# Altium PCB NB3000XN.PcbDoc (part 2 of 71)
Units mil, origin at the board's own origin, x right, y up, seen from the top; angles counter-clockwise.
Board outline 9527.56 x 6929.77 mil, 6 copper layers (Top Layer, GND+SHIELD, MidLayer1, MidLayer2, P2 - 3V3+5V0, Bottom Layer), stack 62.375 mil thick; 832 components, 1027 nets, 4655 pads, 4981 vias.
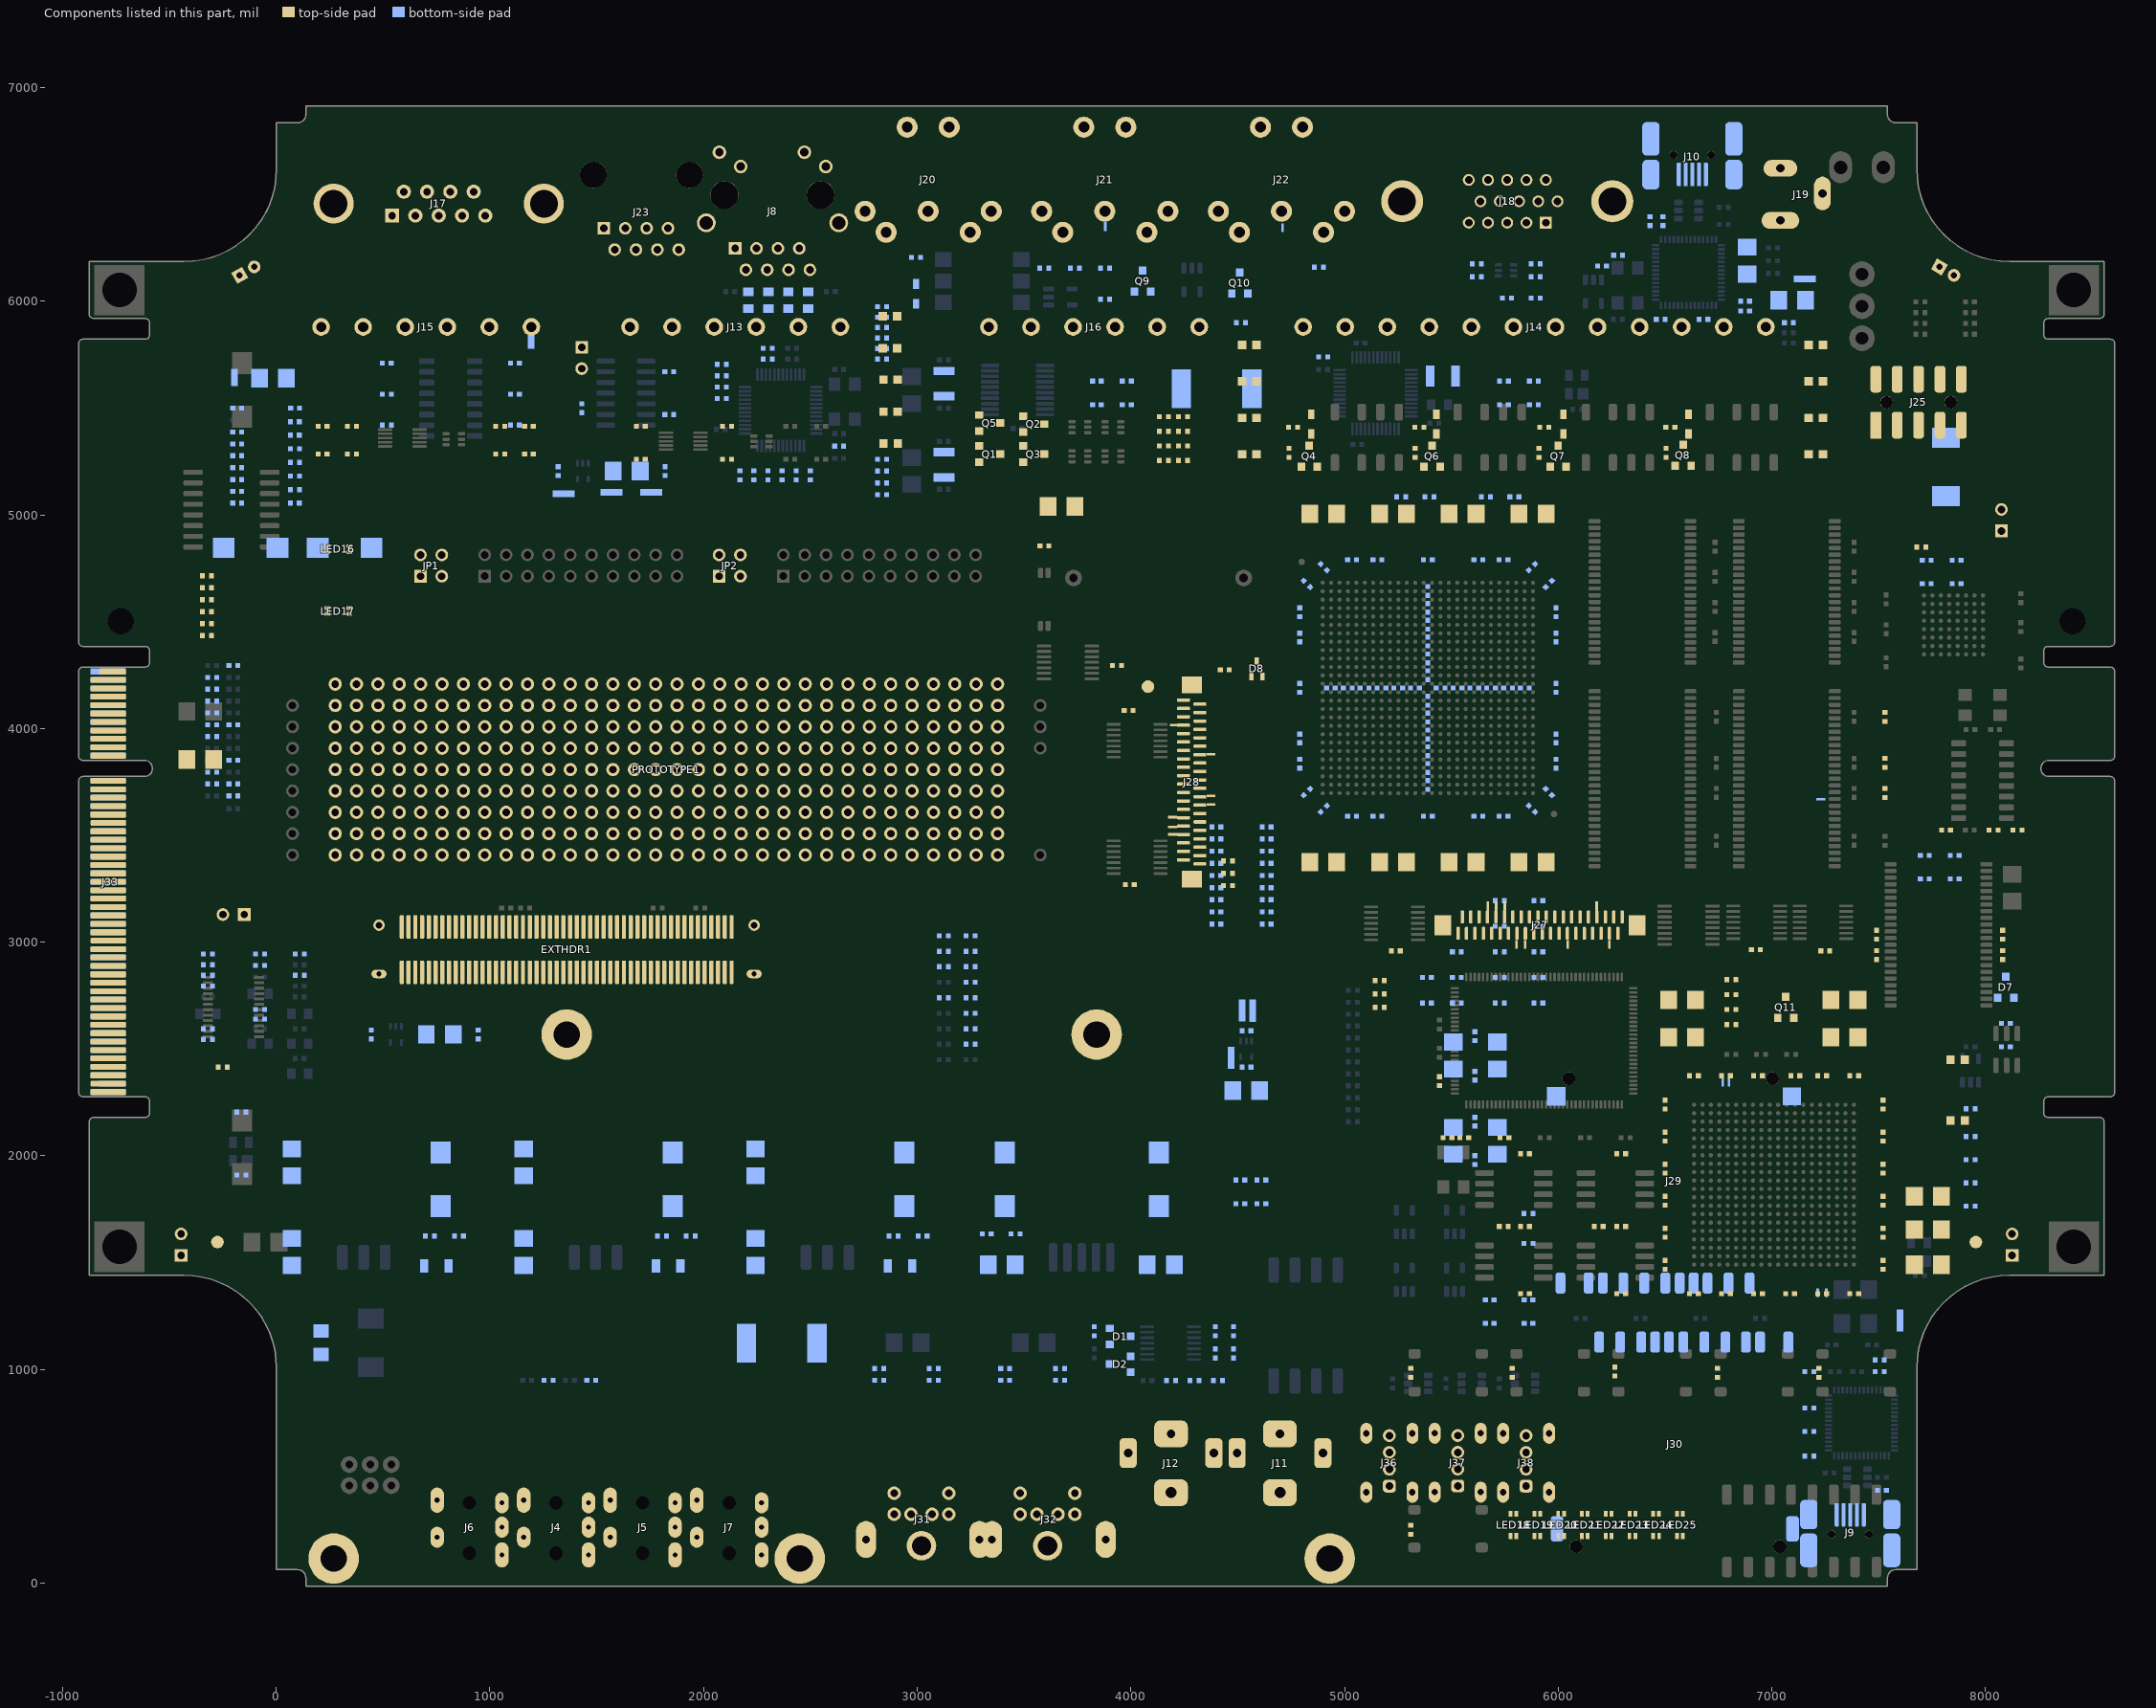
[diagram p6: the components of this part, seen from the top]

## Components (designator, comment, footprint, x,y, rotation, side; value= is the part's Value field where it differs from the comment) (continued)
C106 "220uF 10V" CAPC7343-STAR -120,4845 r180 bottom locked (schematic designator C12)
C107 "220uF 10V" CAPC7343-STAR 320,4845 r180 bottom locked (schematic designator C16)
C108 "1uF 10V" CAPC1005-STAR#1 87.46,5372.94 r180 bottom locked (schematic designator C10)
C109 "1uF 10V" CAPC1005-STAR#1 87.46,5055.08 r0 bottom locked (schematic designator C18)
C110 "1uF 10V" CAPC1005-STAR#1 -182.03,5055.08 r180 bottom locked (schematic designator C14)
C111 "10uF 20V" CAPC3528-STAR#1 -15,5640 r0 bottom locked (schematic designator C23)
C112 "0.1uF 16V" CAPC1005-STAR#1 87.97,5500.08 r180 bottom locked (schematic designator C24)
C113 "0.1uF 16V" CAPC1005-STAR#1 -182.03,5500.08 r180 bottom locked (schematic designator C25)
C114 "0.1uF 16V" CAPC1005-STAR#1 87.46,5436.51 r0 bottom locked (schematic designator C28)
C115 "10uF 20V" CAPC3528-STAR#1 3675,5040 r0 top locked (schematic designator C2)
C116 "0.1uF 16V" CAPC1005-STAR#1 3595,4855 r180 top locked (schematic designator C3)
C117 "33nF 25V" CAPC1005-STAR#1 217,5415 r180 top locked (schematic designator C1)
C118 "33nF 25V" CAPC1005-STAR#1 1183,5415 r0 top locked (schematic designator C2)
C119 "33nF 25V" CAPC1005-STAR#1 1183,5285 r0 top locked (schematic designator C3)
C120 "33nF 25V" CAPC1005-STAR#1 217,5285 r180 top locked (schematic designator C4)
C121 "1uF 10V" CAPC1005-STAR#1 3990,4085 r0 top locked (schematic designator C1)
C122 "1uF 10V" CAPC1005-STAR#1 5240,2960 r0 top locked (schematic designator C1)
C123 "1uF 10V" CAPC1005-STAR#1 6925,2965 r180 top locked (schematic designator C1)
C124 "1uF 10V" CAPC1005-STAR#1 3995,3270 r0 top locked (schematic designator C1)
C125 "1uF 10V" CAPC1005-STAR#1 7250,2960 r0 top locked (schematic designator C1)
C126 "10uF 20V" CAPC3528-STAR#1 2243.07,1550 r90 bottom locked (schematic designator C1)
C127 "1uF 25V" CAPC3216-STAR 2920,1485 r0 bottom locked (schematic designator C2)
C128 "10uF 20V" CAPC3528-STAR#1 2243.07,1970 r90 bottom locked (schematic designator C3)
C129 "220uF 10V" CAPC7343-STAR 2940,1890 r90 bottom locked (schematic designator C4)
C130 "10uF 20V" CAPC3528-STAR#1 1158.07,1550 r90 bottom locked (schematic designator C1)
C131 "1uF 25V" CAPC3216-STAR 1835,1485 r0 bottom locked (schematic designator C2)
C132 "10uF 20V" CAPC3528-STAR#1 1158.07,1970 r90 bottom locked (schematic designator C3)
C133 "220uF 10V" CAPC7343-STAR 1855,1890 r90 bottom locked (schematic designator C4)
C134 "10uF 20V" CAPC3528-STAR#1 73.07,1550 r90 bottom locked (schematic designator C1)
C135 "1uF 25V" CAPC3216-STAR 750,1485 r0 bottom locked (schematic designator C2)
C136 "10uF 20V" CAPC3528-STAR#1 73.07,1970 r90 bottom locked (schematic designator C3)
C137 "220uF 10V" CAPC7343-STAR 770,1890 r90 bottom locked (schematic designator C4)
C138 "220uF 10V" CAPC7343-STAR 4130,1890 r90 bottom locked (schematic designator C1)
C139 "10uF 20V" CAPC3528-STAR#1 4140,1490 r0 bottom locked (schematic designator C2)
C140 "10uF 20V" CAPC3528-STAR#1 3395,1490 r180 bottom locked (schematic designator C3)
C141 "220uF 10V" CAPC7343-STAR 3409.45,1890 r90 bottom locked (schematic designator C4)
C142 "1uF 10V" CAPC1005-STAR#1 4540.98,2585 r180 bottom locked (schematic designator C1)
C143 "10uF 20V" CAPC3528-STAR#1 4540,2305 r0 bottom locked (schematic designator C2)
C144 "1uF 10V" CAPC1005-STAR#1 4540.98,2415 r180 bottom locked (schematic designator C3)
C145 "1uF 10V" CAPC1005-STAR#1 445,2568.37 r270 bottom locked (schematic designator C1)
C146 "10uF 20V" CAPC3528-STAR#2 765.49,2568.37 r180 bottom locked (schematic designator C2)
C147 "1uF 10V" CAPC1005-STAR#1 945,2568.37 r270 bottom locked (schematic designator C3)
C148 "0.1uF 16V" CAPC1005-STAR#1 1117.11,5710.08 r0 bottom locked (schematic designator C1)
C149 "0.1uF 16V" CAPC1005-STAR#1 517.11,5710.08 r0 bottom locked (schematic designator C3)
C150 "0.1uF 16V" CAPC1005-STAR#1 1117.11,5565.08 r0 bottom locked (schematic designator C2)
C151 "0.1uF 16V" CAPC1005-STAR#1 1117.11,5420.08 r0 bottom locked (schematic designator C4)
C152 "1uF 10V" CAPC1005-STAR#1 1840,5470 r0 bottom locked (schematic designator C1)
C153 "0.1uF 16V" CAPC1005-STAR#1 8080,3035 r90 top locked (schematic designator C1_SM)
C154 "0.1uF 16V" CAPC1005-STAR#1 8080,2940 r90 top locked (schematic designator C2_SM)
C155 "10nF 16V" CAPC1005-STAR#1 7490,2940 r90 top locked (schematic designator C3_SM)
C156 "10nF 16V" CAPC1005-STAR#1 7490,3035 r270 top locked (schematic designator C4_SM)
C157 "22pF 50V" CAPC1005-STAR#1 5482,2085 r180 top locked (schematic designator C344)
C158 "10nF 16V" CAPC1005-STAR#1 5745,1670 r0 top locked (schematic designator C1)
C159 "0.1uF 16V" CAPC1005-STAR#1 5845,2010 r180 top locked (schematic designator C2)
C160 "10nF 16V" CAPC1005-STAR#1 6190,1670 r180 top locked (schematic designator C1)
C161 "0.1uF 16V" CAPC1005-STAR#1 6295,1355 r0 top locked (schematic designator C2)
C162 "10nF 16V" CAPC1005-STAR#1 6295,2010 r180 top locked (schematic designator C1)
C163 "0.1uF 16V" CAPC1005-STAR#1 6295,1670 r180 top locked (schematic designator C2)
C164 "10nF 16V" CAPC1005-STAR#1 5845,1670 r180 top locked (schematic designator C3)
C165 "0.1uF 16V" CAPC1005-STAR#1 5845,1355 r180 top locked (schematic designator C4)
C166 "22pF 50V" CAPC1005-STAR#1 6430,6375 r90 bottom locked (schematic designator C1)
C167 "22pF 50V" CAPC1005-STAR#1 6490,6375 r90 bottom locked (schematic designator C2)
C168 "0.1uF 16V" CAPC1005-STAR#1 6280,6215 r180 bottom locked (schematic designator C3)
C169 "22pF 50V" CAPC1005-STAR#1 5560,2085 r180 top locked (schematic designator C345)
C170 "0.1uF 16V" CAPC1005-STAR#1 7080,5900 r180 bottom locked (schematic designator C2)
C171 "10uF 20V" CAPC3528-STAR#1 7095,6005 r0 bottom locked (schematic designator C6)
C172 "0.1uF 16V" CAPC1005-STAR#1 6205,6165 r180 bottom locked (schematic designator C3)
C173 "0.1uF 16V" CAPC1005-STAR#1 6680,5915 r0 bottom locked (schematic designator C4)
C174 "0.1uF 16V" CAPC1005-STAR#1 6480,5915 r180 bottom locked (schematic designator C5)
C175 "10uF 20V" CAPC3528-STAR#1 6885,6190 r90 bottom locked (schematic designator C7)
C176 "0.1uF 16V" CAPC1005-STAR#1 6875,5955 r180 bottom locked (schematic designator C8)
C177 "0.1uF 16V" CAPC1005-STAR#1 6875,6000 r180 bottom locked (schematic designator C9)
C181 "1uF 10V" CAPC1005-STAR#1 1320,5205 r270 bottom locked (schematic designator C1)
C182 "10uF 20V" CAPC3528-STAR#1 1640.49,5205 r180 bottom locked (schematic designator C2)
C183 "1uF 10V" CAPC1005-STAR#1 1820,5205 r270 bottom locked (schematic designator C3)
C184 "10uF 20V" CAPC3528-STAR#1 7340,2730 r0 top locked (schematic designator C42_FP)
C185 "10uF 20V" CAPC3528-STAR#1 5715,2070 r270 bottom locked (schematic designator C343)
C186 "220nF 16V" CAPC1005-STAR#1 5445,2350 r270 top locked (schematic designator C205)
C187 "0.1uF 16V" CAPC1005-STAR#1 5748.74,2085 r0 top locked (schematic designator C204)
C189 "10uF 20V" CAPC3528-STAR#1 6580,2730 r180 top locked (schematic designator C1_FP)
C190 "10uF 20V" CAPC3528-STAR#1 7730,1810 r0 top locked (schematic designator C2_FP)
C191 "10uF 20V" CAPC3528-STAR#1 -355,3855 r180 top locked (schematic designator C3_FP)
C192 "0.1uF 16V" CAPC1005-STAR#1 5386.06,2715 r0 bottom locked (schematic designator C5_FP)
C193 "0.1uF 16V" CAPC1005-STAR#1 5386.06,2835 r0 bottom locked (schematic designator C8_FP)
C194 "0.1uF 16V" CAPC1005-STAR#1 7520,1940 r90 top locked (schematic designator C9_FP)
C195 "0.1uF 16V" CAPC1005-STAR#1 7520,1790 r270 top locked (schematic designator C11_FP)
C196 "10nF 16V" CAPC1005-STAR#1 6935,2375 r180 top locked (schematic designator C13_FP)
C197 "10nF 16V" CAPC1005-STAR#1 7110,2375 r0 top locked (schematic designator C15_FP)
C198 "10nF 16V" CAPC1005-STAR#1 6935,1355 r180 top locked (schematic designator C16_FP)
C199 "10nF 16V" CAPC1005-STAR#1 7085,1355 r0 top locked (schematic designator C18_FP)
C200 "10uF 20V" CAPC3528-STAR#1 7730,1655 r0 top locked (schematic designator C38_FP)
C201 "10uF 20V" CAPC3528-STAR#1 7340,2555 r0 top locked (schematic designator C39_FP)
C202 "10uF 20V" CAPC3528-STAR#1 6580,2555 r180 top locked (schematic designator C40_FP)
C203 "10uF 20V" CAPC3528-STAR#1 7730,1490 r0 top locked (schematic designator C41_FP)
C215 "0.1uF 16V" CAPC1005-STAR#1 6635,2375 r0 top locked (schematic designator C46_FP)
C216 "0.1uF 16V" CAPC1005-STAR#1 4512.39,1776.18 r180 bottom locked (schematic designator C47_FP)
C217 "0.1uF 16V" CAPC1005-STAR#1 7235,2375 r0 top locked (schematic designator C48_FP)
C218 "0.1uF 16V" CAPC1005-STAR#1 7520,2240 r90 top locked (schematic designator C49_FP)
C219 "0.1uF 16V" CAPC1005-STAR#1 5679.72,1326.18 r0 bottom locked (schematic designator C50_FP)
C220 "0.1uF 16V" CAPC1005-STAR#1 7520,1640 r90 top locked (schematic designator C51_FP)
C221 "0.1uF 16V" CAPC1005-STAR#1 6635,1355 r0 top locked (schematic designator C52_FP)
C222 "0.1uF 16V" CAPC1005-STAR#1 7716.06,3296.18 r180 bottom locked (schematic designator C53_FP)
C223 "0.1uF 16V" CAPC1005-STAR#1 7235,1355 r0 top locked (schematic designator C54_FP)
C224 "0.1uF 16V" CAPC1005-STAR#1 6500,2240 r90 top locked (schematic designator C55_FP)
C225 "0.1uF 16V" CAPC1005-STAR#1 5886.06,5626.18 r180 bottom locked (schematic designator C56_FP)
C226 "0.1uF 16V" CAPC1005-STAR#1 5886.06,5516.18 r180 bottom locked (schematic designator C57_FP)
C227 "0.1uF 16V" CAPC1005-STAR#1 7724.33,4788 r180 bottom locked (schematic designator C58_FP)
C228 "0.1uF 16V" CAPC1005-STAR#1 7724.33,4678 r180 bottom locked (schematic designator C59_FP)
C229 "0.1uF 16V" CAPC1005-STAR#1 3981.06,5626.18 r180 bottom locked (schematic designator C60_FP)
C231 "10nF 16V" CAPC1005-STAR#1 6785,2375 r0 top locked (schematic designator C62_FP)
C232 "10nF 16V" CAPC1005-STAR#1 4512.39,1886.18 r180 bottom locked (schematic designator C63_FP)
C233 "10nF 16V" CAPC1005-STAR#1 7385,2375 r0 top locked (schematic designator C64_FP)
C234 "10nF 16V" CAPC1005-STAR#1 7520,2090 r90 top locked (schematic designator C65_FP)
C235 "10nF 16V" CAPC1005-STAR#1 5679.72,1216.18 r0 bottom locked (schematic designator C66_FP)
C236 "10nF 16V" CAPC1005-STAR#1 7520,1490 r90 top locked (schematic designator C67_FP)
C237 "10nF 16V" CAPC1005-STAR#1 6785,1355 r0 top locked (schematic designator C68_FP)
C238 "10nF 16V" CAPC1005-STAR#1 7716.06,3406.18 r180 bottom locked (schematic designator C69_FP)
C239 "10nF 16V" CAPC1005-STAR#1 7385,1355 r0 top locked (schematic designator C70_FP)
C240 "10nF 16V" CAPC1005-STAR#1 6500,2090 r90 top locked (schematic designator C71_FP)
C241 "10nF 16V" CAPC1005-STAR#1 6500,1790 r90 top locked (schematic designator C73_FP)
C242 "10nF 16V" CAPC1005-STAR#1 6500,1490 r90 top locked (schematic designator C74_FP)
C243 "10nF 16V" CAPC1005-STAR#1 3841.06,5626.18 r0 bottom locked (schematic designator C79_FP)
C244 "10nF 16V" CAPC1005-STAR#1 3841.06,5516.18 r0 bottom locked (schematic designator C80_FP)
C245 "10nF 16V" CAPC1005-STAR#1 6500,1940 r90 top locked (schematic designator C81_FP)
C246 "10nF 16V" CAPC1005-STAR#1 6500,1640 r90 top locked (schematic designator C84_FP)
C247 "0.1uF 16V" CAPC1005-STAR#1 7864.33,4788 r0 bottom locked (schematic designator C85_FP)
C248 "10nF 16V" CAPC1005-STAR#1 7864.33,4678 r180 bottom locked (schematic designator C101_FP)
C249 "0.1uF 16V" CAPC1005-STAR#1 5861.06,1326.18 r180 bottom locked (schematic designator C87_FP)
C250 "10nF 16V" CAPC1005-STAR#1 5861.06,1216.18 r180 bottom locked (schematic designator C88_FP)
C251 "10nF 16V" CAPC1005-STAR#1 4611.06,1886.18 r180 bottom locked (schematic designator C89_FP)
C252 "0.1uF 16V" CAPC1005-STAR#1 4611.06,1776.18 r180 bottom locked (schematic designator C100_FP)
C253 "10nF 16V" CAPC1005-STAR#1 7856.06,3406.18 r180 bottom locked (schematic designator C91_FP)
C254 "10nF 16V" CAPC1005-STAR#1 7856.06,3296.18 r180 bottom locked (schematic designator C99_FP)
C255 "0.1uF 16V" CAPC1005-STAR#1 5746.06,5626.18 r180 bottom locked (schematic designator C98_FP)
C256 "10nF 16V" CAPC1005-STAR#1 5746.06,5516.18 r180 bottom locked (schematic designator C94_FP)
C257 "0.1uF 16V" CAPC1005-STAR#1 5526.06,2835 r180 bottom (schematic designator C95_FP)
C258 "10nF 16V" CAPC1005-STAR#1 5526.06,2715 r180 bottom locked (schematic designator C96_FP)
C259 "0.1uF 16V" CAPC1005-STAR#1 3981.06,5516.18 r180 bottom locked (schematic designator C97_FP)
C260 "10uF 20V" CAPC3528-STAR#1 5227.32,5005 r180 top locked (schematic designator C42_FP)
C265 "10uF 20V" CAPC3528-STAR#1 5227.32,3375 r180 top locked (schematic designator C1_FP)
C266 "10uF 20V" CAPC3528-STAR#1 5552.68,3375 r0 top locked (schematic designator C2_FP)
C267 "10uF 20V" CAPC3528-STAR#1 5552.68,5005 r0 top locked (schematic designator C3_FP)
C268 "0.1uF 16V" CAPC1005-STAR#2 5390,4250.04 r90 bottom locked (schematic designator C5_FP)
C269 "0.1uF 16V" CAPC1005-STAR#2 5450.04,4190 r0 bottom locked (schematic designator C8_FP)
C270 "0.1uF 16V" CAPC1005-STAR#2 5390,4129.96 r270 bottom locked (schematic designator C9_FP)
C271 "0.1uF 16V" CAPC1005-STAR#2 5329.96,4190 r180 bottom locked (schematic designator C11_FP)
C272 "10nF 16V" CAPC1005-STAR#2 5390,4328.78 r90 bottom locked (schematic designator C13_FP)
C273 "10nF 16V" CAPC1005-STAR#2 5528.78,4190 r0 bottom locked (schematic designator C15_FP)
C274 "10nF 16V" CAPC1005-STAR#2 5390,4051.22 r270 bottom locked (schematic designator C16_FP)
C275 "10nF 16V" CAPC1005-STAR#2 5251.22,4190 r180 bottom locked (schematic designator C18_FP)
C276 "10uF 20V" CAPC3528-STAR#1 4900,5005 r180 top locked (schematic designator C38_FP)
C277 "10uF 20V" CAPC3528-STAR#1 5880,5005 r0 top locked (schematic designator C39_FP)
C278 "10uF 20V" CAPC3528-STAR#1 4900,3375 r180 top locked (schematic designator C40_FP)
C279 "10uF 20V" CAPC3528-STAR#1 5880,3375 r0 top locked (schematic designator C41_FP)
C291 "0.1uF 16V" CAPC1005-STAR#2 5626.22,4790 r180 bottom locked (schematic designator C46_FP)
C292 "0.1uF 16V" CAPC1005-STAR#2 5153.78,4790 r0 bottom locked (schematic designator C47_FP)
C293 "0.1uF 16V" CAPC1005-STAR#2 5877.06,4755.8 r45 bottom locked (schematic designator C48_FP)
C294 "0.1uF 16V" CAPC1005-STAR#2 4902.94,4755.8 r135 bottom locked (schematic designator C49_FP)
C295 "0.1uF 16V" CAPC1005-STAR#2 5390,4407.52 r90 bottom locked (schematic designator C50_FP)
C296 "0.1uF 16V" CAPC1005-STAR#2 5607.52,4190 r0 bottom locked (schematic designator C51_FP)
C297 "0.1uF 16V" CAPC1005-STAR#2 5390,3972.48 r270 bottom locked (schematic designator C52_FP)
C298 "0.1uF 16V" CAPC1005-STAR#2 5172.48,4190 r180 bottom locked (schematic designator C53_FP)
C299 "0.1uF 16V" CAPC1005-STAR#2 5390,4565 r90 bottom locked (schematic designator C54_FP)
C300 "0.1uF 16V" CAPC1005-STAR#2 5765,4190 r0 bottom locked (schematic designator C55_FP)
C301 "0.1uF 16V" CAPC1005-STAR#2 5390,3815 r270 bottom locked (schematic designator C56_FP)
C302 "0.1uF 16V" CAPC1005-STAR#2 5015,4190 r180 bottom locked (schematic designator C57_FP)
C303 "0.1uF 16V" CAPC1005-STAR#2 5990,4544.33 r90 bottom locked (schematic designator C58_FP)
C304 "0.1uF 16V" CAPC1005-STAR#2 4790,4544.33 r90 bottom locked (schematic designator C59_FP)
C305 "0.1uF 16V" CAPC1005-STAR#2 5990,3953.78 r90 bottom locked (schematic designator C60_FP)
C307 "10nF 16V" CAPC1005-STAR#2 5744.33,4790 r180 bottom locked (schematic designator C62_FP)
C308 "10nF 16V" CAPC1005-STAR#2 5035.67,4790 r0 bottom locked (schematic designator C63_FP)
C309 "10nF 16V" CAPC1005-STAR#2 5955.8,4677.06 r45 bottom locked (schematic designator C64_FP)
C310 "10nF 16V" CAPC1005-STAR#2 4824.2,4677.06 r135 bottom locked (schematic designator C65_FP)
C311 "10nF 16V" CAPC1005-STAR#2 5390,4486.26 r270 bottom locked (schematic designator C66_FP)
C312 "10nF 16V" CAPC1005-STAR#2 5686.26,4190 r180 bottom locked (schematic designator C67_FP)
C313 "10nF 16V" CAPC1005-STAR#2 5390,3893.74 r90 bottom locked (schematic designator C68_FP)
C314 "10nF 16V" CAPC1005-STAR#2 5093.74,4190 r0 bottom locked (schematic designator C69_FP)
C315 "10nF 16V" CAPC1005-STAR#2 5390,4643.74 r270 bottom locked (schematic designator C70_FP)
C316 "10nF 16V" CAPC1005-STAR#2 5843.74,4190 r180 bottom locked (schematic designator C71_FP)
C317 "10nF 16V" CAPC1005-STAR#2 5390,3736.26 r90 bottom locked (schematic designator C73_FP)
C318 "10nF 16V" CAPC1005-STAR#2 4936.26,4190 r0 bottom locked (schematic designator C74_FP)
C319 "10nF 16V" CAPC1005-STAR#2 5990,4426.22 r90 bottom locked (schematic designator C79_FP)
C320 "10nF 16V" CAPC1005-STAR#2 4790,4426.22 r270 bottom locked (schematic designator C80_FP)
C321 "10nF 16V" CAPC1005-STAR#2 5990,3835.67 r270 bottom locked (schematic designator C81_FP)
C322 "10nF 16V" CAPC1005-STAR#2 4790,3835.67 r270 bottom locked (schematic designator C84_FP)
C323 "0.1uF 16V" CAPC1005-STAR#2 4790,3953.78 r90 bottom locked (schematic designator C85_FP)
C324 "10nF 16V" CAPC1005-STAR#2 5877.06,3624.2 r315 bottom locked (schematic designator C101_FP)
C325 "0.1uF 16V" CAPC1005-STAR#2 5955.8,3702.94 r315 bottom locked (schematic designator C87_FP)
C326 "10nF 16V" CAPC1005-STAR#2 4902.94,3624.2 r225 bottom locked (schematic designator C88_FP)
C327 "10nF 16V" CAPC1005-STAR#2 4824.2,3702.94 r225 bottom locked (schematic designator C89_FP)
C328 "0.1uF 16V" CAPC1005-STAR#2 5626.22,3590 r180 bottom locked (schematic designator C100_FP)
C329 "10nF 16V" CAPC1005-STAR#2 5744.33,3590 r180 bottom locked (schematic designator C91_FP)
C330 "10nF 16V" CAPC1005-STAR#2 5153.78,3590 r0 bottom locked (schematic designator C99_FP)
C331 "0.1uF 16V" CAPC1005-STAR#2 5035.67,3590 r0 bottom locked (schematic designator C98_FP)
C332 "10nF 16V" CAPC1005-STAR#2 5390,4790 r0 bottom locked (schematic designator C94_FP)
C333 "0.1uF 16V" CAPC1005-STAR#2 5390,3590 r180 bottom locked (schematic designator C95_FP)
C334 "10nF 16V" CAPC1005-STAR#2 5990,4190 r90 bottom locked (schematic designator C96_FP)
C335 "0.1uF 16V" CAPC1005-STAR#2 4790,4190 r270 bottom locked (schematic designator C97_FP)
C336 "0.1uF 16V" CAPC1005-STAR#1 5610,2560 r90 bottom locked (schematic designator C3)
C337 "0.1uF 16V" CAPC1005-STAR#1 5610,2375 r90 bottom locked (schematic designator C4)
C338 "0.1uF 16V" CAPC1005-STAR#1 5610,2160 r90 bottom locked (schematic designator C5)
C339 "0.1uF 16V" CAPC1005-STAR#1 5610,1980 r90 bottom locked (schematic designator C6)
C340 "10uF 20V" CAPC3528-STAR#1 5510,2470 r270 bottom locked (schematic designator C7)
C341 "10uF 20V" CAPC3528-STAR#1 5510,2070 r270 bottom locked (schematic designator C8)
C342 "10uF 20V" CAPC3528-STAR#1 5715,2470 r270 bottom locked (schematic designator C9)
D1 "200mA 30V" SOT95P230-3C 3950,1155 r90 bottom locked
D2 "200mA 30V" SOT95P230-3C 3950,1025 r270 bottom locked
D3 "ZHCS400" SOD323 4845,5425 r90 top locked (schematic designator D1)
D4 "ZHCS400" SOD323 5430,5425 r90 top locked (schematic designator D1)
D5 "ZHCS400" SOD323 6025,5425 r90 top locked (schematic designator D1)
D6 "ZHCS400" SOD323 6610,5425 r90 top locked (schematic designator D1)
D7 "3.3V" SOT95P230-3D 8095,2789 r180 bottom locked (schematic designator D1)
D8 "BAT54CW-3" SOT323-3AL 4590,4280 r90 top locked (schematic designator D1)
D9 "ZHCS400" SOD323 2995,6035 r270 bottom locked (schematic designator D1)
D10 "5V 5W" DIOM8059 7814.9,5225 r90 bottom locked
EXTHDR1 "NANOCONNECT" 53751 1359.67,2965.55 r180 top locked (schematic designator EXTHDR)
F1 "MF-SM250" MF_SM250 4475,5585 r180 bottom locked
F2 "MF-SM250" MF_SM250 2440,1118.58 r180 bottom locked
FD1 "Fiducial - Round" "FIDUCIAL ROUND" -274.99,1596.61 r90 top locked
FD2 "Fiducial - Round" "FIDUCIAL ROUND" 4080,4196.25 r90 top locked
FD3 "Fiducial - Round" "FIDUCIAL ROUND" 7955,1596.61 r90 top locked
J1 "1x2 HEADER MALE" HDR1X2 -445,1535 r90 top locked
J2 "1x2 HEADER MALE" HDR1X2 -150,3130 r180 top locked
J3 "1x2 HEADER MALE" HDR1X2 8125,1535 r90 top locked
J4 "AUDIO BLACK HEADER" TSH-3675 1310,140 r90 bottom locked (schematic designator J1)
J5 "AUDIO GREEN HEADER" TSH-3675 1715,140 r90 bottom locked (schematic designator J3)
J6 "AUDIO BLUE HEADER" TSH-3675 905,140 r90 bottom locked (schematic designator J4)
J7 "AUDIO BLACK HEADER" TSH-3675 2120,140 r90 bottom locked (schematic designator J5)
J8 "RJ45_LEDS" CON_RJ45_RA_LEDS 2323,6497.49 r0 bottom locked (schematic designator J1)
J9 "USB MINI" KME04-USBMU03A01-1 7430,320 r90 bottom locked (schematic designator J1)
J10 "USB MINI" KME04-USBMU03A01-1 6565,6594 r270 bottom locked (schematic designator J1)
J11 "RCA Header" TRC-005 4697.98,699.39 r90 bottom locked (schematic designator J1)
J12 "RCA Header" TRC-005 4187.98,699.39 r90 bottom locked (schematic designator J2)
J13 "KMRJ103-5.0/508 6WAYS" KMRJ103-5-508-6 2148.35,5880 r0 top locked (schematic designator J1)
J14 "KMRJ103-5.0/508 12WAYS" KMRJ103-5-508-12 5889.2,5880 r0 top locked (schematic designator J4)
J15 "KMRJ103-5.0/508 6WAYS" KMRJ103-5-508-6 702.26,5880 r0 top locked (schematic designator J2)
J16 "KMRJ103-5.0/508 6WAYS" KMRJ103-5-508-6 3828.04,5880.01 r0 top locked (schematic designator J3)
J17 "DRB-09P11G1R" DB9_MALE 597,6513 r180 bottom locked (schematic designator J1)
J18 "HDR-15S11G1R" DB15-VGA-FEMALE 5942,6368 r180 bottom locked (schematic designator J1)
J19 "POWERJACK 3 HEADER" KLD-0202 7040,6918 r270 bottom locked (schematic designator J1)
J20 "KMFCDIN76005" KMFCDIN76005 3051.46,6569 r0 bottom locked (schematic designator J1)
J21 "KMFCDIN76005" KMFCDIN76005 3878.23,6569 r0 bottom locked (schematic designator J2)
J22 "KMFCDIN76005" KMFCDIN76005 4705,6569 r0 bottom locked (schematic designator J3)
J23 "955012881" 955012881 1709,6477 r0 bottom locked (schematic designator J1)
J24 "1x2 HEADER MALE" HDR1X2 8075,4925.76 r90 top locked (schematic designator J1)
J25 "TSM-105-01-S-DV" TSM-105-01-DV 7486.99,5635.25 r0 top locked (schematic designator J1)
J26 "1x2 HEADER MALE" HDR1X2 1429.42,5784.24 r270 top locked (schematic designator J1)
J27 "2x20 FFC VERT" FPC-XXS1VN3R 5915.42,3080 r180 top locked
J28 "2x20 FFC VERT" FPC-XXS1VN3R 4285,3750 r270 top locked (schematic designator J1)
J29 "SD CARD HEADER" KSDC012551#1 6542.3,1883 r180 bottom locked (schematic designator J1)
J30 "SD CARD HEADER" KSDC012551#2 6545.55,650 r0 bottom locked (schematic designator J1)
J31 "MINIDIN 6P" MINIDIN6PURPLE 3020,-10 r90 bottom locked (schematic designator J1)
J32 "MINIDIN 6P" MINIDIN6PURPLE 3610,-10 r90 bottom locked (schematic designator J1)
J33 "Diagnostics Interface" EDGE-PCIE-X8 -923.78,4267.03 r90 top locked (schematic designator J1)
J34 "1x2 PH" PH-2 -171.19,6121.57 r30 bottom (schematic designator J37)
J35 "1x2 PH" PH-2 7784.36,6160.94 r330 bottom (schematic designator J38)
J36 "USB A UPRIGHT" 482040001 5209.9,150 r180 bottom locked (schematic designator J34)
J37 "USB A UPRIGHT" 482040001 5529.9,150.39 r180 bottom locked (schematic designator J34)
J38 "USB A UPRIGHT" 482040001 5849.9,150 r180 bottom locked (schematic designator J34)
JP1 "2x2 HEADER MALE" HDR2X2 675.1,4713.08 r0 top locked
JP2 "2x2 HEADER MALE" HDR2X2 2072.74,4713.08 r0 top locked
L1 "22uH 250mA 0.71R" INDC3225 3125,5235 r270 bottom locked
L2 "22uH 250mA 0.71R" INDC3225 3125,5615 r270 bottom locked
L3 "4.7uH 650mA 0.15R" INDC3225 5460,5650 r180 bottom locked (schematic designator L1)
LED1 "LED, Green, 0603 (1608)" 0603LED_GREEN 7870,2450 r180 top locked
LED2 "LED, 0603, Yellow (1608)" 0603LED_YELLOW 7870,2165 r180 top locked
LED3 "LED, Green, 0603 (1608)" 0603LED_GREEN 2872.68,5779.97 r0 top locked
LED4 "LED, Green, 0603 (1608)" 0603LED_GREEN 2872.74,5930 r0 top locked
LED5 "LED, 0603, Yellow (1608)" 0603LED_YELLOW 2875.55,5633.26 r0 top locked (schematic designator LED2)
LED6 "LED, 0603, Orange (1608)" 0603LED_ORANGE 2875.55,5483.47 r0 top locked
LED7 "0603 LED" 0603LED_RED 2875.6,5333.71 r0 top locked (schematic designator LED3)
LED8 "LED, 0603, Yellow (1608)" 0603LED_YELLOW 4553.95,5624.9 r0 top locked (schematic designator LED1)
LED9 "LED, 0603, Yellow (1608)" 0603LED_YELLOW 4553.95,5454.52 r0 top locked (schematic designator LED1)
LED10 "LED, 0603, Yellow (1608)" 0603LED_YELLOW 4553.95,5284.13 r0 top locked (schematic designator LED1)
LED11 "LED, 0603, Orange (1608)" 0603LED_ORANGE 7205.66,5795.28 r0 top locked (schematic designator LED1)
LED12 "LED, 0603, Yellow (1608)" 0603LED_YELLOW 4553.95,5795.29 r0 top locked (schematic designator LED1)
LED13 "LED, 0603, Orange (1608)" 0603LED_ORANGE 7205.66,5624.9 r0 top locked (schematic designator LED1)
LED14 "LED, 0603, Orange (1608)" 0603LED_ORANGE 7205.66,5454.51 r0 top locked (schematic designator LED1)
LED15 "LED, 0603, Orange (1608)" 0603LED_ORANGE 7205.66,5284.12 r0 top locked (schematic designator LED1)
LED16 "S1204RGBSDJC" S1204RGBSDJC 290.31,4840 r180 top locked (schematic designator LED1)
LED17 "S1204RGBSDJC" S1204RGBSDJC 290.31,4550 r180 top locked (schematic designator LED2)
LED18 "S1204RGBSDJC" S1204RGBSDJC 5790.95,272.51 r90 top locked (schematic designator LED1)
LED19 "S1204RGBSDJC" S1204RGBSDJC 5902.2,272.51 r90 top locked (schematic designator LED2)
LED20 "S1204RGBSDJC" S1204RGBSDJC 6013.45,272.51 r90 top locked (schematic designator LED1)
LED21 "S1204RGBSDJC" S1204RGBSDJC 6124.7,272.51 r90 top locked (schematic designator LED2)
LED22 "S1204RGBSDJC" S1204RGBSDJC 6235.94,272.51 r90 top locked (schematic designator LED1)
LED23 "S1204RGBSDJC" S1204RGBSDJC 6347.19,272.51 r90 top locked (schematic designator LED2)
LED24 "S1204RGBSDJC" S1204RGBSDJC 6458.44,272.51 r90 top locked (schematic designator LED1)
LED25 "S1204RGBSDJC" S1204RGBSDJC 6569.68,272.51 r90 top locked (schematic designator LED2)
LOGO1 "Nanoboard Logo" "NANOBOARD LOGO" 720,4460 r180 bottom locked
NT1 "Net Tie SMT2" NETTIE-SMT2-31X39 -195,5690 r90 bottom locked net-tie
NT4 "Net Tie SMT2" NETTIE-SMT2-8X8#1 7254.76,1322.8 r270 bottom locked net-tie (schematic designator NT2)
NT5 "Net Tie SMT2" NETTIE-SMT2-8X8#2 6770,2380 r90 bottom locked net-tie (schematic designator NT3)
NT6 "Net Tie SMT2" NETTIE-SMT2-8X8#3 7215,1322.8 r270 bottom locked net-tie (schematic designator NT4)
NT7 "Net Tie SMT2" NETTIE-SMT2-8X8#4 6801.11,2380 r90 bottom locked net-tie (schematic designator NT5)
NT10 "Net Tie SMT2" NETTIE-SMT2-31X51 7600,1220 r270 bottom locked net-tie (schematic designator NT1)
NT11 "Net Tie SMT2" NETTIE-SMT2-31X39 1194.15,5771.57 r270 bottom locked net-tie
NT17 "Net Tie SMT2" NETTIE-SMT2-31X51 1745,5105 r180 bottom locked net-tie (schematic designator NT2)
NT18 "Net Tie SMT2" NETTIE-SMT2-31X51 1355,5100 r0 bottom locked net-tie (schematic designator NT1)
NT19 "Net Tie SMT2" NETTIE-SMT2-31X51 1560,5105 r180 bottom locked net-tie (schematic designator NT3)
NT26 "Net Tie SMT2" NETTIE-SMT2-8X8#5 4174.92,3582.44 r180 top locked net-tie (schematic designator NT1)
NT27 "Net Tie SMT2" NETTIE-SMT2-8X8#6 4174.92,3543.07 r180 top locked net-tie (schematic designator NT2)
NT28 "Net Tie SMT2" NETTIE-SMT2-8X8#7 4182,4012 r180 top locked net-tie (schematic designator NT3)
NT29 "Net Tie SMT2" NETTIE-SMT2-8X8#8 4333.78,3877.72 r180 top locked net-tie (schematic designator NT4)
NT30 "Net Tie SMT2" NETTIE-SMT2-8X8#9 4396.06,3641.97 r0 top locked net-tie (schematic designator NT5)
NT31 "Net Tie SMT2" NETTIE-SMT2-8X8#10 4174.92,3503.7 r180 top locked net-tie (schematic designator NT6)
NT33 "Net Tie SMT2" NETTIE-SMT2-8X8#11 4396.06,3681.34 r0 top locked net-tie (schematic designator NT8)
NT34 "Net Tie SMT2" NETTIE-SMT2-8X8#12 6240.46,2970 r270 top locked net-tie
NT35 "Net Tie SMT2" NETTIE-SMT2-8X8#13 5747.86,3190 r90 top locked net-tie
NT36 "Net Tie SMT2" NETTIE-SMT2-8X8#14 5708.49,3190 r90 top locked net-tie
NT37 "Net Tie SMT2" NETTIE-SMT2-8X8#15 5846.76,2970 r270 top locked net-tie
NT38 "Net Tie SMT2" NETTIE-SMT2-8X8#16 6043.61,2970 r270 top locked net-tie
NT39 "Net Tie SMT2" NETTIE-SMT2-8X8#17 6180.93,3190 r90 top locked net-tie
NT40 "Net Tie SMT2" NETTIE-SMT2-8X8#18 5669.12,3190 r90 top locked net-tie
NT41 "Net Tie SMT2" NETTIE-SMT2-8X8#19 5807.39,2970 r270 top locked net-tie
NT42 "Net Tie SMT2" NETTIE-SMT2-31X51 4470,2450 r270 bottom locked net-tie (schematic designator NT10)
NT43 "Net Tie SMT2" NETTIE-SMT2-31X51 4520,2690 r90 bottom locked net-tie (schematic designator NT9)
NT44 "Net Tie SMT2" NETTIE-SMT2-31X51 4570,2670 r270 bottom locked net-tie (schematic designator NT11)
NT45 "Net Tie SMT2" NETTIE-SMT2-31X51 7145,6105 r180 bottom locked net-tie (schematic designator NT1)
NT46 "Net Tie SMT2" NETTIE-SMT2-8X8#20 7259,3669 r0 bottom locked net-tie (schematic designator NT3)
NT47 "Net Tie SMT2" NETTIE-SMT2-8X8#20 3880,6380 r90 bottom locked net-tie
NT48 "Net Tie SMT2" NETTIE-SMT2-8X8#21 4710,6365 r90 bottom locked net-tie
PB_MH1 "8.5mm spacer, Gold, 2xM3" STANDOFF_SOLDER_3MM#1 1359.67,2567.91 r180 top locked
PB_MH2 "8.5mm spacer, Gold, 2xM3" STANDOFF_SOLDER_3MM#2 269.12,115.16 r180 top locked
PB_MH3 "8.5mm spacer, Gold, 2xM3" STANDOFF_SOLDER_3MM#2 2450.22,115.16 r270 top locked
PB_MH4 "8.5mm spacer, Gold, 2xM3" STANDOFF_SOLDER_3MM#2 3839.98,2567.91 r180 top locked
PB_MH5 "8.5mm spacer, Gold, 2xM3" STANDOFF_SOLDER_3MM#2 4930.53,115.16 r270 top locked
PBFREE "" LEAD_FREE_S 4035,4895 r180 bottom
PBOARD_A "Comment" PERIPHERAL_BOARD_1SLOT 2580.16,3213.57 r180 top locked
PBOARD_B "Comment" PERIPHERAL_BOARD_1SLOT 5060.46,3213.58 r180 top locked
PCB1 "NB2STR01 Blank PCB" "NB2STR01 Blank PCB" 1379,1235 r180 bottom
PROTOTYPE1 "" TESTPOINT_ARRAY 276.12,3408.23 r0 top locked (schematic designator PROTOTYPE)
Q1 "AO3400" SOT95P230-3D 3340,5285 r270 top locked
Q2 "AO3400" SOT95P230-3D 3545,5425 r270 top locked (schematic designator Q1)
Q3 "AO3400" SOT95P230-3D 3545,5285 r270 top locked (schematic designator Q1)
Q4 "2N7002" SOT95P230-3D 4835,5275 r0 top locked (schematic designator Q1)
Q5 "AO3400" SOT95P230-3D 3340,5430 r270 top locked (schematic designator Q1)
Q6 "2N7002" SOT95P230-3D 5410,5275 r0 top locked (schematic designator Q1)
Q7 "2N7002" SOT95P230-3D 6000,5275 r0 top locked (schematic designator Q1)
Q8 "2N7002" SOT95P230-3D 6585,5280 r0 top locked (schematic designator Q1)
Q9 "2N7002" SOT95P230-3D 4055,6095 r180 bottom locked (schematic designator Q1)
Q10 "2N7002" SOT95P230-3D 4510,6085 r180 bottom locked (schematic designator Q1)
Q11 "AO3400" SOT95P230-3D 7065,2695 r0 top locked
R1 "3K3 1%" RESC1005-STAR -200,3851.36 r180 bottom locked
R2 "10K 1%" RESC1005-STAR -300,3795.91 r0 bottom locked
R3 "47K 1%" RESC1005-STAR 1475,950 r180 bottom locked (schematic designator R14)
R4 "47K 1%" RESC1005-STAR 1275.01,950 r180 bottom locked (schematic designator R15)
R5 "10K 1%" RESC1005-STAR -300,3740.45 r0 bottom locked (schematic designator R3)
R6 "10K 1%" RESC1005-STAR -200,3740.45 r180 bottom locked (schematic designator R4)
R7 "10K 1%" RESC1005-STAR -200,3685 r180 bottom locked (schematic designator R5)
R8 "22K 1%" RESC1005-STAR -300,3962.27 r180 bottom locked (schematic designator R6)
R9 "100K 1%" RESC1005-STAR -200,4017.73 r180 bottom locked (schematic designator R7)
R10 "10K 1%" RESC1005-STAR -300,4017.73 r180 bottom locked (schematic designator R8)
R11 "10K 1%" RESC1005-STAR -300,4073.18 r180 bottom locked (schematic designator R9)
R12 "10K 1%" RESC1005-STAR -300,4128.64 r180 bottom locked (schematic designator R10)
R13 "10K 1%" RESC1005-STAR -300,4184.09 r180 bottom locked (schematic designator R11)
R14 "3K3 1%" RESC1005-STAR -200,4295 r180 bottom locked (schematic designator R12)
R15 "10K 1%" RESC1005-STAR -300,4239.55 r180 bottom locked (schematic designator R13)
R16 "33R 1%" RESC1005-STAR -320,2795 r180 bottom locked (schematic designator R1)
R17 "33R 1%" RESC1005-STAR -320,2845 r180 bottom locked (schematic designator R2)
R18 "33R 1%" RESC1005-STAR -320,2945 r0 bottom locked (schematic designator R3)
R19 "33R 1%" RESC1005-STAR -320,2545 r180 bottom locked (schematic designator R4)
R20 "33R 1%" RESC1005-STAR -320,2895 r0 bottom locked (schematic designator R5)
R21 "10K 1%" RESC1005-STAR -320,2595 r0 bottom locked (schematic designator R6)
R22 "4K7 1%" RESC1005-STAR -75,2640 r180 bottom locked (schematic designator R7)
R23 "430R 1%" RESC1005-STAR 110,2845 r180 bottom locked (schematic designator R8)
R24 "430R 1%" RESC1005-STAR 110,2945 r180 bottom locked (schematic designator R9)
R25 "4K7 1%" RESC1005-STAR -75,2685 r180 bottom locked (schematic designator R10)
R26 "4K7 1%" RESC1005-STAR -75,2891.25 r180 bottom locked (schematic designator R11)
R27 "4K7 1%" RESC1005-STAR -75,2945 r180 bottom locked (schematic designator R12)
R28 "5R6 1%" RESC1005-STAR 8150,3525 r0 top locked (schematic designator R1)
R29 "5R6 1%" RESC1005-STAR 7815,3525 r180 top locked (schematic designator R2)
R30 "1K 1%" RESC1005-STAR 8038.33,3525 r180 top locked (schematic designator R3)
R31 "120R 1%" RESC1005-STAR 4480,1180 r270 bottom locked (schematic designator R1)
R32 "120R 1%" RESC1005-STAR 4480,1075 r270 bottom locked (schematic designator R2)
R33 "33R 1%" RESC1005-STAR 4407,949 r0 bottom (schematic designator R3)
R34 "75R 1%" RESC1005-STAR 4297.34,949 r180 bottom (schematic designator R4)
R35 "10K 1%" RESC1005-STAR 4395,1180 r270 bottom locked (schematic designator R6)
R36 "75R 1%" RESC1005-STAR 3829,1180 r90 bottom locked (schematic designator R8)
R37 "100R 1%" RESC1005-STAR 4187.68,949 r180 bottom (schematic designator R7)
R38 "10K 1%" RESC1005-STAR 4395,1075 r90 bottom (schematic designator R5)
R39 "270R 1%" RESC1005-STAR 7930,2220 r0 bottom locked (schematic designator R1)
R40 "270R 1%" RESC1005-STAR 7930,2090 r0 bottom locked (schematic designator R2)
R41 "4K7 1%" RESC1005-STAR 2434,5185 r270 bottom locked (schematic designator R1)
R42 "4K7 1%" RESC1005-STAR 2368,5185 r270 bottom locked (schematic designator R2)
R43 "4K7 1%" RESC1005-STAR 2302,5185 r270 bottom locked (schematic designator R3)
R44 "4K7 1%" RESC1005-STAR 2236,5185 r270 bottom locked (schematic designator R4)
R45 "4K7 1%" RESC1005-STAR 2170,5185 r270 bottom locked (schematic designator R5)
R46 "4K7 1%" RESC1005-STAR 2085,5705 r180 bottom locked (schematic designator R6)
R47 "4K7 1%" RESC1005-STAR 2085,5651.67 r180 bottom locked (schematic designator R7)
R48 "49R9 1%" RESC2012-STAR 2303.31,6005 r90 bottom locked (schematic designator R8)
R49 "49R9 1%" RESC2012-STAR 2210,6005 r90 bottom locked (schematic designator R9)
R50 "4K7 1%" RESC1005-STAR 2500,5185 r90 bottom locked (schematic designator R10)
R51 "4K7 1%" RESC1005-STAR 2085,5598.33 r180 bottom locked (schematic designator R11)
R52 "4K7 1%" RESC1005-STAR 2085,5545 r180 bottom locked (schematic designator R12)
R53 "1K 1%" RESC1005-STAR 2300,5730 r0 bottom locked (schematic designator R13)
R54 "49R9 1%" RESC2012-STAR 2396.69,6005 r270 bottom locked (schematic designator R14)
R55 "49R9 1%" RESC2012-STAR 2490,6005 r270 bottom locked (schematic designator R15)
R56 "1K 1%" RESC1005-STAR 2300,5780 r180 bottom locked (schematic designator R16)
R57 "4K7 1%" RESC1005-STAR 2835,5828 r180 bottom locked (schematic designator R17)
R58 "470R 1%" RESC1005-STAR 2835,5877 r0 bottom locked (schematic designator R18)
R59 "4K7 1%" RESC1005-STAR 2635,5322.5 r0 bottom locked (schematic designator R19)
R60 "4K7 1%" RESC1005-STAR 2835,5926 r180 bottom locked (schematic designator R20)
R61 "4K7 1%" RESC1005-STAR 2835,5150 r0 bottom locked (schematic designator R21)
R62 "470R 1%" RESC1005-STAR 2835,5975 r0 bottom locked (schematic designator R22)
R63 "470R 1%" RESC1005-STAR 2835,5095 r0 bottom locked (schematic designator R23)
R64 "4K7 1%" RESC1005-STAR 2835,5730 r0 bottom locked (schematic designator R24)
R65 "4K7 1%" RESC1005-STAR 2835,5205 r0 bottom locked (schematic designator R25)
R66 "470R 1%" RESC1005-STAR 2835,5779 r180 bottom locked (schematic designator R26)
R67 "470R 1%" RESC1005-STAR 2835,5260 r0 bottom locked (schematic designator R27)
R68 "100R 1%" RESC1005-STAR 5727,3195 r180 bottom locked (schematic designator R8)
R69 "100R 1%" RESC1005-STAR 5727,3075 r180 bottom locked (schematic designator R9)
R70 "4K7 1%" RESC1005-STAR 5662.5,5085 r180 bottom locked (schematic designator R1)
R71 "100R 1%" RESC1005-STAR 5727,2955 r180 bottom locked (schematic designator R10)
R72 "100R 1%" RESC1005-STAR 5727,2835 r180 bottom locked (schematic designator R12)
R73 "4K7 1%" RESC1005-STAR 5526.06,2955 r180 bottom (schematic designator R2)
R74 "100R 1%" RESC1005-STAR 5727,2715 r180 bottom locked (schematic designator R24)
R75 "100R 1%" RESC1005-STAR 5907,2715 r180 bottom locked (schematic designator R22)
R76 "4K7 1%" RESC1005-STAR 5397.5,5085 r180 bottom locked (schematic designator R3)
R77 "4K7 1%" RESC1005-STAR 5265,5085 r180 bottom locked (schematic designator R4)
R78 "100R 1%" RESC1005-STAR 5907,3195 r180 bottom locked (schematic designator R20)
R79 "100R 1%" RESC1005-STAR 5907,3075 r180 bottom locked (schematic designator R14)
R80 "100R 1%" RESC1005-STAR 5907,2955 r180 bottom locked (schematic designator R18)
R81 "100R 1%" RESC1005-STAR 5907,2835 r180 bottom locked (schematic designator R23)
R82 "4K7 1%" RESC1005-STAR 2822.05,950 r180 bottom locked (schematic designator R1)
R83 "4K7 1%" RESC1005-STAR 3077.95,950 r180 bottom locked (schematic designator R2)
R84 "100R 1%" RESC1005-STAR 3077.95,1005 r180 bottom locked (schematic designator R3)
R85 "100R 1%" RESC1005-STAR 2822.05,1005 r180 bottom locked (schematic designator R4)
R86 "4K7 1%" RESC1005-STAR 3412.05,950 r180 bottom locked (schematic designator R1)
R87 "4K7 1%" RESC1005-STAR 3667.95,950 r180 bottom locked (schematic designator R2)
R88 "100R 1%" RESC1005-STAR 3667.95,1005 r180 bottom locked (schematic designator R3)
R89 "100R 1%" RESC1005-STAR 3412.05,1005 r180 bottom locked (schematic designator R4)
R90 "27R 1%" RESC1005-STAR 4155,5391.67 r0 top locked (schematic designator R2)
R91 "1K 1%" RESC1005-STAR 4245,5391.67 r0 top locked (schematic designator R1)
R92 "27R 1%" RESC1005-STAR 4155,5323.33 r0 top locked (schematic designator R2)
R93 "1K 1%" RESC1005-STAR 4245,5323.33 r0 top locked (schematic designator R1)
R94 "27R 1%" RESC1005-STAR 4155,5255 r0 top locked (schematic designator R2)
R95 "1K 1%" RESC1005-STAR 4245,5255 r0 top locked (schematic designator R1)
R96 "120R 1%" RESC1005-STAR 4740,5290 r270 top locked (schematic designator R1)
R97 "1K 1%" RESC1005-STAR 4760,5410 r180 top locked (schematic designator R2)
R98 "4K7 1%" RESC1005-STAR -162.5,2205 r0 bottom locked
R99 "2K2 1%" RESC1005-STAR -250,2415 r0 top locked
R100 "5R6 1%" RESC1005-STAR 6810,2825 r0 top locked
R101 "5R6 1%" RESC1005-STAR 6810,2755 r0 top locked
R102 "4K7 1%" RESC1005-STAR 5310,985 r270 top locked (schematic designator R1)
R103 "4K7 1%" RESC1005-STAR 5785,985 r270 top locked (schematic designator R2)
R104 "4K7 1%" RESC1005-STAR 6265,990 r90 top locked (schematic designator R3)
R105 "4K7 1%" RESC1005-STAR 6745,985 r270 top locked (schematic designator R4)
R106 "4K7 1%" RESC1005-STAR 7220,985 r90 top locked (schematic designator R5)
R107 "4K7 1%" RESC1005-STAR 5310,250 r90 top locked (schematic designator R1)
R108 "2K7 1%" RESC1005-STAR 7505,990 r0 bottom locked (schematic designator R2)
R109 "5K6 1%" RESC1005-STAR 7505,1045 r0 bottom locked (schematic designator R3)
R110 "10K 1%" RESC1005-STAR 7515,435 r180 bottom locked (schematic designator R4)
R111 "10M 1%" RESC3216 210,1125 r270 bottom locked (schematic designator R248)
R112 "27R 1%" RESC1005-STAR 7175,595 r0 bottom locked (schematic designator R6)
R113 "4K7 1%" RESC1005-STAR 7175,710 r180 bottom locked (schematic designator R9)
R114 "4K7 1%" RESC1005-STAR 7175,820 r180 bottom locked (schematic designator R8)
R115 "4K7 1%" RESC1005-STAR 7175,990 r180 bottom locked (schematic designator R7)
R116 "430R 1%" RESC1005-STAR 4900,5740 r0 bottom locked (schematic designator R1)
R117 "150R 1%" RESC1005-STAR 5895,6015 r0 bottom locked (schematic designator R2)
R118 "150R 1%" RESC1005-STAR 5760,6015 r0 bottom locked (schematic designator R3)
R119 "150R 1%" RESC1005-STAR 5620,6115 r180 bottom locked (schematic designator R4)
R120 "150R 1%" RESC1005-STAR 5620,6175 r0 bottom locked (schematic designator R5)
R121 "150R 1%" RESC1005-STAR 5895,6175 r180 bottom locked (schematic designator R6)
R122 "150R 1%" RESC1005-STAR 5895,6115 r180 bottom locked (schematic designator R7)
R123 "27R 1%" RESC1005-STAR 4155,5460 r0 top locked (schematic designator R2)
R124 "1K 1%" RESC1005-STAR 4245,5460 r0 top locked (schematic designator R1)
R125 "120R 1%" RESC1005-STAR 5330,5290 r270 top locked (schematic designator R1)
R126 "1K 1%" RESC1005-STAR 5350,5410 r0 top locked (schematic designator R2)
R127 "120R 1%" RESC1005-STAR 5910,5290 r270 top locked (schematic designator R1)
R128 "1K 1%" RESC1005-STAR 5935,5410 r180 top locked (schematic designator R2)
R129 "120R 1%" RESC1005-STAR 6505,5290 r270 top locked (schematic designator R1)
R130 "1K 1%" RESC1005-STAR 6525,5410 r180 top locked (schematic designator R2)
R131 "4K7 1%" RESC1005-STAR 8095,2510 r180 bottom locked (schematic designator R2)
R132 "470R 1%" RESC1005-STAR 8095,2620 r180 bottom locked (schematic designator R1)
R133 "27R 1%" RESC1005-STAR 1705.87,5260 r0 top locked (schematic designator R1)
R134 "27R 1%" RESC1005-STAR 1705.87,5415 r0 top locked (schematic designator R2)
R135 "27R 1%" RESC1005-STAR 2110.87,5415 r180 top locked (schematic designator R3)
R136 "27R 1%" RESC1005-STAR 2110.87,5260 r180 top locked (schematic designator R4)
R137 "10K 1%" RESC1005-STAR -182.03,5388.42 r180 bottom locked (schematic designator R11)
R138 "10K 1%" RESC1005-STAR -182.03,5276.75 r180 bottom locked (schematic designator R18)
R139 "1K 1%" RESC1005-STAR -182.03,5220.92 r0 bottom locked (schematic designator R16)
R140 "1K 1%" RESC1005-STAR -182.03,5110.08 r0 bottom locked (schematic designator R13)
R141 "100K 1%" RESC1005-STAR 87.97,5182.22 r0 bottom locked (schematic designator R10)
R142 "100K 1%" RESC1005-STAR 87.46,5245.8 r180 bottom locked (schematic designator R19)
R143 "1K 1%" RESC1005-STAR 87.46,5118.65 r0 bottom locked (schematic designator R21)
R144 "1K 1%" RESC1005-STAR -182.03,5332.58 r0 bottom locked (schematic designator R26)
R145 "2K2 1%" RESC1005-STAR -182.03,5165.08 r0 bottom locked (schematic designator R25)
R146 "2K2 1%" RESC1005-STAR 87.46,5309.37 r180 bottom locked (schematic designator R27)
R147 "100R 1%" RESC1005-STAR 4440,4275 r0 top locked (schematic designator R1)
R148 "4K7 1%" RESC1005-STAR 3935,4295 r0 top locked (schematic designator R1)
R149 "27R 1%" RESC1005-STAR 355,5415 r0 top locked (schematic designator R1)
R150 "27R 1%" RESC1005-STAR 1048.82,5415 r180 top locked (schematic designator R2)
R151 "27R 1%" RESC1005-STAR 1048.82,5285 r180 top locked (schematic designator R3)
R152 "27R 1%" RESC1005-STAR 355,5285 r0 top locked (schematic designator R4)
R153 "5R6 1%" RESC1005-STAR 5795,5085 r0 bottom locked (schematic designator R1_HOST)
R154 "4K7 1%" RESC1005-STAR -162.5,1910 r180 bottom locked
R155 "2K2 1%" RESC1005-STAR 7530,4055 r270 top locked (schematic designator R272)
R156 "2K2 1%" RESC1005-STAR 7530,3839.49 r270 top locked (schematic designator R273)
R157 "2K2 1%" RESC1005-STAR 7530,3698.78 r270 top locked (schematic designator R274)
R158 "2K2 1%" RESC1005-STAR 5861.06,1730 r0 bottom locked (schematic designator R1)
R159 "2K2 1%" RESC1005-STAR 7700,4850 r180 top locked (schematic designator R2)
R160 "2K2 1%" RESC1005-STAR 5861.06,1590 r0 bottom locked (schematic designator R3)
R161 "4K7 1%" RESC1005-STAR 7930,1873.33 r180 bottom locked (schematic designator R1)
R162 "4K7 1%" RESC1005-STAR 7930,1765 r180 bottom locked (schematic designator R2)
R163 "4K7 1%" RESC1005-STAR 7930,1981.67 r180 bottom locked (schematic designator R3)
R164 "150R 1%" RESC1005-STAR -325,4715 r180 top locked (schematic designator R1)
R165 "150R 1%" RESC1005-STAR -325,4603 r180 top locked (schematic designator R2)
R166 "150R 1%" RESC1005-STAR -325,4659 r180 top locked (schematic designator R3)
R167 "150R 1%" RESC1005-STAR -325,4547 r180 top locked (schematic designator R4)
R168 "150R 1%" RESC1005-STAR -325,4435 r180 top locked (schematic designator R5)
R169 "150R 1%" RESC1005-STAR -325,4491 r180 top locked (schematic designator R6)
R170 "150R 1%" RESC1005-STAR 4455,3380 r180 top locked (schematic designator R1)
R171 "150R 1%" RESC1005-STAR 4455,3265 r180 top locked (schematic designator R2)
R172 "150R 1%" RESC1005-STAR 4455,3322.5 r180 top locked (schematic designator R3)
R173 "150R 1%" RESC1005-STAR 5165,2820 r180 top locked (schematic designator R4)
R174 "150R 1%" RESC1005-STAR 5165,2695 r180 top locked (schematic designator R5)
R175 "150R 1%" RESC1005-STAR 5165,2757.5 r180 top locked (schematic designator R6)
R176 "150R 1%" RESC1005-STAR 4400,3198.75 r0 bottom locked (schematic designator R1)
R177 "150R 1%" RESC1005-STAR 4400,3085 r0 bottom locked (schematic designator R2)
R178 "150R 1%" RESC1005-STAR 4400,3141.88 r0 bottom locked (schematic designator R3)
R179 "150R 1%" RESC1005-STAR 4400,3369.38 r0 bottom locked (schematic designator R4)
R180 "150R 1%" RESC1005-STAR 4400,3255.62 r0 bottom locked (schematic designator R5)
R181 "150R 1%" RESC1005-STAR 4400,3312.5 r0 bottom locked (schematic designator R6)
R182 "150R 1%" RESC1005-STAR 4400,3540 r0 bottom locked (schematic designator R1)
R183 "150R 1%" RESC1005-STAR 4400,3426.25 r0 bottom locked (schematic designator R2)
R184 "150R 1%" RESC1005-STAR 4400,3483.12 r0 bottom locked (schematic designator R3)
R185 "150R 1%" RESC1005-STAR 4635,3198.75 r0 bottom locked (schematic designator R4)
R186 "150R 1%" RESC1005-STAR 4635,3085 r0 bottom locked (schematic designator R5)
R187 "150R 1%" RESC1005-STAR 4635,3141.88 r0 bottom locked (schematic designator R6)
R188 "150R 1%" RESC1005-STAR 4635,3369.38 r0 bottom locked (schematic designator R1)
R189 "150R 1%" RESC1005-STAR 4635,3255.62 r0 bottom locked (schematic designator R2)
R190 "150R 1%" RESC1005-STAR 4635,3312.5 r0 bottom locked (schematic designator R3)
R191 "150R 1%" RESC1005-STAR 4635,3540 r0 bottom locked (schematic designator R4)
R192 "150R 1%" RESC1005-STAR 4635,3426.25 r0 bottom locked (schematic designator R5)
R193 "150R 1%" RESC1005-STAR 4635,3483.12 r0 bottom locked (schematic designator R6)
R194 "220R 1%" RESC1005-STAR 2995,6205 r0 bottom locked (schematic designator R2)
R195 "470R 1%" RESC1005-STAR 3737.5,6155 r0 bottom locked (schematic designator R1)
R196 "27R 1%" RESC1005-STAR 3595,6155 r180 bottom locked (schematic designator R3)
R197 "220R 1%" RESC1005-STAR 3880,6155 r0 bottom locked (schematic designator R5)
R198 "120R 1%" RESC1005-STAR 3880,6010 r0 bottom locked (schematic designator R4)
R199 "220R 1%" RESC1005-STAR 4880,6160 r0 bottom locked (schematic designator R7)
R200 "120R 1%" RESC1005-STAR 4515,5900 r0 bottom locked (schematic designator R6)
R201 "120R 1%" RESC1005-STAR 2890,1625 r180 bottom locked (schematic designator R1)
R202 "56R 1%" RESC1005-STAR 3025,1625 r0 bottom locked (schematic designator R2)
R203 "120R 1%" RESC1005-STAR 1805,1625 r180 bottom locked (schematic designator R1)
R204 "120R 1%" RESC1005-STAR 1940,1625 r0 bottom locked (schematic designator R2)
R205 "120R 1%" RESC1005-STAR 720,1625 r180 bottom locked (schematic designator R1)
R206 "200R 1%" RESC1005-STAR 855,1625 r0 bottom locked (schematic designator R2)
R207 "0R 5%" RESC1005-STAR 3325,1635 r180 bottom locked (schematic designator R1)
R208 "10K 1%" RESC1005-STAR 3460,1635 r0 bottom locked (schematic designator R2)
R209 "100R 1%" RESC1005-STAR 517.11,5565.08 r0 bottom locked (schematic designator R1)
R210 "100R 1%" RESC1005-STAR 517.11,5420.08 r0 bottom locked (schematic designator R2)
R211 "100R 1%" RESC1005-STAR 1840,5670 r180 bottom locked (schematic designator R1)
R212 "120R 1%" RESC1005-STAR 1430,5500 r90 bottom locked (schematic designator R2)
R214 "120R 1%" RESC1005-STAR 6810,2615 r0 top locked
R215 "47K 1%" RESC1005-STAR 6810,2685 r0 top locked (schematic designator R2)
R216 "4K7 1%" RESC1005-STAR 3250,3030 r0 bottom locked (schematic designator R1)
R217 "4K7 1%" RESC1005-STAR 3250,2957.5 r0 bottom locked (schematic designator R2)
R218 "4K7 1%" RESC1005-STAR 3250,2740 r0 bottom locked (schematic designator R3)
R219 "4K7 1%" RESC1005-STAR 3250,2885 r0 bottom locked (schematic designator R4)
R220 "100R 1%" RESC1005-STAR 3125,3030 r180 bottom locked (schematic designator R5)
R221 "100R 1%" RESC1005-STAR 3125,2957.5 r180 bottom locked (schematic designator R6)
R222 "100R 1%" RESC1005-STAR 3125,2740 r180 bottom locked (schematic designator R7)
R223 "100R 1%" RESC1005-STAR 3125,2885 r180 bottom locked (schematic designator R8)
R224 "4K7 1%" RESC1005-STAR 3250,2812.5 r0 bottom locked (schematic designator R9)
R225 "4K7 1%" RESC1005-STAR 3250,2667.5 r0 bottom locked (schematic designator R10)
R226 "4K7 1%" RESC1005-STAR 3250,2522.5 r180 bottom locked (schematic designator R11)
R227 "4K7 1%" RESC1005-STAR 3250,2595 r0 bottom locked (schematic designator R12)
